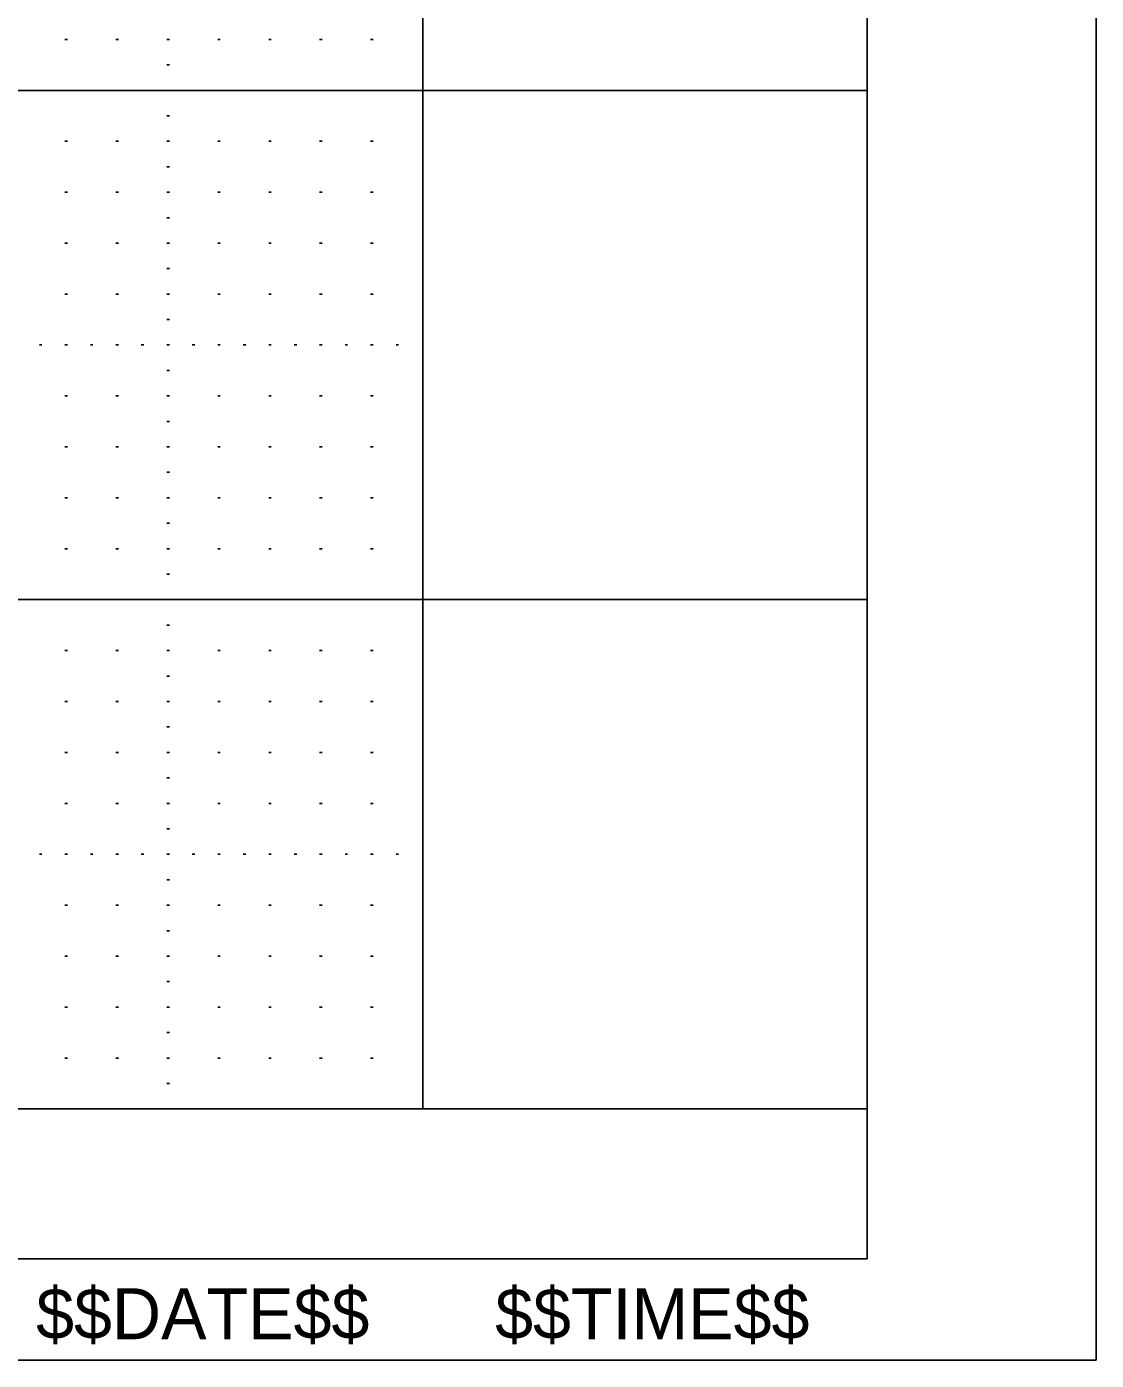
# Model space of a CAD drawing. Extents: x -1.3 to 32.1, y -0.2 to 20.7.
# Drawn here: x 29.967 to 32.067, y -0.2 to 2.418 of the extents above; entities that cross this region are included whole.
import ezdxf

# ---------------------------------------------------------------- set-up
doc = ezdxf.new("R2010")
doc.units = 0
for name, color, linetype in [('Level 1', 7, 'Continuous'), ('Level 4', 7, 'Continuous'), ('Level 48', 7, 'Continuous'), ('Level 5', 7, 'Continuous'), ('Level 63', 7, 'Continuous'), ('R_Border_Dark', 7, 'Continuous')]:
    doc.layers.add(name, color=color, linetype=linetype)

msp = doc.modelspace()

# ---------------------------------------------------------------- linework, layer by layer
at = {"layer": 'Level 1'}
for q in [(31.617, 20.545), (-0.001, -0.001)]:
    msp.add_line((31.617, -0.001), q, dxfattribs=at)
at = {"layer": 'Level 4'}
msp.add_line((31.617, 0.293), (-0.001, 0.293), dxfattribs=at)
at = {"layer": 'Level 5'}
for p, q in [((30.0425, 2.393), (30.0475, 2.393)), ((30.1425, 2.393), (30.1475, 2.393)), ((30.2425, 2.393), (30.2475, 2.393)), ((30.3425, 2.393), (30.3475, 2.393)), ((30.4425, 2.393), (30.4475, 2.393)), ((30.5425, 2.393), (30.5475, 2.393)), ((30.6425, 2.393), (30.6475, 2.393)), ((30.2425, 2.343), (30.2475, 2.343)), ((30.2425, 2.243), (30.2475, 2.243)), ((30.0425, 2.193), (30.0475, 2.193)), ((30.1425, 2.193), (30.1475, 2.193)), ((30.2425, 2.193), (30.2475, 2.193)), ((30.3425, 2.193), (30.3475, 2.193)), ((30.4425, 2.193), (30.4475, 2.193)), ((30.5425, 2.193), (30.5475, 2.193)), ((30.6425, 2.193), (30.6475, 2.193)), ((30.2425, 2.143), (30.2475, 2.143)), ((30.0425, 2.093), (30.0475, 2.093)), ((30.1425, 2.093), (30.1475, 2.093)), ((30.2425, 2.093), (30.2475, 2.093)), ((30.3425, 2.093), (30.3475, 2.093)), ((30.4425, 2.093), (30.4475, 2.093)), ((30.5425, 2.093), (30.5475, 2.093)), ((30.6425, 2.093), (30.6475, 2.093)), ((30.2425, 2.043), (30.2475, 2.043)), ((30.0425, 1.993), (30.0475, 1.993)), ((30.1425, 1.993), (30.1475, 1.993)), ((30.2425, 1.993), (30.2475, 1.993)), ((30.3425, 1.993), (30.3475, 1.993)), ((30.4425, 1.993), (30.4475, 1.993)), ((30.5425, 1.993), (30.5475, 1.993)), ((30.6425, 1.993), (30.6475, 1.993)), ((30.2425, 1.943), (30.2475, 1.943)), ((30.0425, 1.893), (30.0475, 1.893)), ((30.1425, 1.893), (30.1475, 1.893)), ((30.2425, 1.893), (30.2475, 1.893)), ((30.3425, 1.893), (30.3475, 1.893)), ((30.4425, 1.893), (30.4475, 1.893)), ((30.5425, 1.893), (30.5475, 1.893)), ((30.6425, 1.893), (30.6475, 1.893)), ((30.2425, 1.843), (30.2475, 1.843)), ((29.9925, 1.793), (29.9975, 1.793)), ((30.0425, 1.793), (30.0475, 1.793)), ((30.0925, 1.793), (30.0975, 1.793)), ((30.1425, 1.793), (30.1475, 1.793)), ((30.1925, 1.793), (30.1975, 1.793)), ((30.2425, 1.793), (30.2475, 1.793)), ((30.2925, 1.793), (30.2975, 1.793)), ((30.3425, 1.793), (30.3475, 1.793)), ((30.3925, 1.793), (30.3975, 1.793)), ((30.4425, 1.793), (30.4475, 1.793)), ((30.4925, 1.793), (30.4975, 1.793)), ((30.5425, 1.793), (30.5475, 1.793)), ((30.5925, 1.793), (30.5975, 1.793)), ((30.6425, 1.793), (30.6475, 1.793)), ((30.6925, 1.793), (30.6975, 1.793)), ((30.2425, 1.743), (30.2475, 1.743)), ((30.0425, 1.693), (30.0475, 1.693)), ((30.1425, 1.693), (30.1475, 1.693)), ((30.2425, 1.693), (30.2475, 1.693)), ((30.3425, 1.693), (30.3475, 1.693)), ((30.4425, 1.693), (30.4475, 1.693)), ((30.5425, 1.693), (30.5475, 1.693)), ((30.6425, 1.693), (30.6475, 1.693)), ((30.2425, 1.643), (30.2475, 1.643)), ((30.0425, 1.593), (30.0475, 1.593)), ((30.1425, 1.593), (30.1475, 1.593)), ((30.2425, 1.593), (30.2475, 1.593)), ((30.3425, 1.593), (30.3475, 1.593)), ((30.4425, 1.593), (30.4475, 1.593)), ((30.5425, 1.593), (30.5475, 1.593)), ((30.6425, 1.593), (30.6475, 1.593)), ((30.2425, 1.543), (30.2475, 1.543)), ((30.0425, 1.493), (30.0475, 1.493)), ((30.1425, 1.493), (30.1475, 1.493)), ((30.2425, 1.493), (30.2475, 1.493)), ((30.3425, 1.493), (30.3475, 1.493)), ((30.4425, 1.493), (30.4475, 1.493)), ((30.5425, 1.493), (30.5475, 1.493)), ((30.6425, 1.493), (30.6475, 1.493)), ((30.2425, 1.443), (30.2475, 1.443)), ((30.0425, 1.393), (30.0475, 1.393)), ((30.1425, 1.393), (30.1475, 1.393)), ((30.2425, 1.393), (30.2475, 1.393)), ((30.3425, 1.393), (30.3475, 1.393)), ((30.4425, 1.393), (30.4475, 1.393)), ((30.5425, 1.393), (30.5475, 1.393)), ((30.6425, 1.393), (30.6475, 1.393)), ((30.2425, 1.343), (30.2475, 1.343)), ((30.2425, 1.243), (30.2475, 1.243)), ((30.0425, 1.193), (30.0475, 1.193)), ((30.1425, 1.193), (30.1475, 1.193)), ((30.2425, 1.193), (30.2475, 1.193)), ((30.3425, 1.193), (30.3475, 1.193)), ((30.4425, 1.193), (30.4475, 1.193)), ((30.5425, 1.193), (30.5475, 1.193)), ((30.6425, 1.193), (30.6475, 1.193)), ((30.2425, 1.143), (30.2475, 1.143)), ((30.0425, 1.093), (30.0475, 1.093)), ((30.1425, 1.093), (30.1475, 1.093)), ((30.2425, 1.093), (30.2475, 1.093)), ((30.3425, 1.093), (30.3475, 1.093)), ((30.4425, 1.093), (30.4475, 1.093)), ((30.5425, 1.093), (30.5475, 1.093)), ((30.6425, 1.093), (30.6475, 1.093)), ((30.2425, 1.043), (30.2475, 1.043)), ((30.0425, 0.993), (30.0475, 0.993)), ((30.1425, 0.993), (30.1475, 0.993)), ((30.2425, 0.993), (30.2475, 0.993)), ((30.3425, 0.993), (30.3475, 0.993)), ((30.4425, 0.993), (30.4475, 0.993)), ((30.5425, 0.993), (30.5475, 0.993)), ((30.6425, 0.993), (30.6475, 0.993)), ((30.2425, 0.943), (30.2475, 0.943)), ((30.0425, 0.893), (30.0475, 0.893)), ((30.1425, 0.893), (30.1475, 0.893)), ((30.2425, 0.893), (30.2475, 0.893)), ((30.3425, 0.893), (30.3475, 0.893)), ((30.4425, 0.893), (30.4475, 0.893)), ((30.5425, 0.893), (30.5475, 0.893)), ((30.6425, 0.893), (30.6475, 0.893)), ((30.2425, 0.843), (30.2475, 0.843)), ((29.9925, 0.793), (29.9975, 0.793)), ((30.0425, 0.793), (30.0475, 0.793)), ((30.0925, 0.793), (30.0975, 0.793)), ((30.1425, 0.793), (30.1475, 0.793)), ((30.1925, 0.793), (30.1975, 0.793)), ((30.2425, 0.793), (30.2475, 0.793)), ((30.2925, 0.793), (30.2975, 0.793)), ((30.3425, 0.793), (30.3475, 0.793)), ((30.3925, 0.793), (30.3975, 0.793)), ((30.4425, 0.793), (30.4475, 0.793)), ((30.4925, 0.793), (30.4975, 0.793)), ((30.5425, 0.793), (30.5475, 0.793)), ((30.5925, 0.793), (30.5975, 0.793)), ((30.6425, 0.793), (30.6475, 0.793)), ((30.6925, 0.793), (30.6975, 0.793)), ((30.2425, 0.743), (30.2475, 0.743)), ((30.0425, 0.693), (30.0475, 0.693)), ((30.1425, 0.693), (30.1475, 0.693)), ((30.2425, 0.693), (30.2475, 0.693)), ((30.3425, 0.693), (30.3475, 0.693)), ((30.4425, 0.693), (30.4475, 0.693)), ((30.5425, 0.693), (30.5475, 0.693)), ((30.6425, 0.693), (30.6475, 0.693)), ((30.2425, 0.643), (30.2475, 0.643)), ((30.0425, 0.593), (30.0475, 0.593)), ((30.1425, 0.593), (30.1475, 0.593)), ((30.2425, 0.593), (30.2475, 0.593)), ((30.3425, 0.593), (30.3475, 0.593)), ((30.4425, 0.593), (30.4475, 0.593)), ((30.5425, 0.593), (30.5475, 0.593)), ((30.6425, 0.593), (30.6475, 0.593)), ((30.2425, 0.543), (30.2475, 0.543)), ((30.0425, 0.493), (30.0475, 0.493)), ((30.1425, 0.493), (30.1475, 0.493)), ((30.2425, 0.493), (30.2475, 0.493)), ((30.3425, 0.493), (30.3475, 0.493)), ((30.4425, 0.493), (30.4475, 0.493)), ((30.5425, 0.493), (30.5475, 0.493)), ((30.6425, 0.493), (30.6475, 0.493)), ((30.2425, 0.443), (30.2475, 0.443)), ((30.0425, 0.393), (30.0475, 0.393)), ((30.1425, 0.393), (30.1475, 0.393)), ((30.2425, 0.393), (30.2475, 0.393)), ((30.3425, 0.393), (30.3475, 0.393)), ((30.4425, 0.393), (30.4475, 0.393)), ((30.5425, 0.393), (30.5475, 0.393)), ((30.6425, 0.393), (30.6475, 0.393)), ((30.2425, 0.343), (30.2475, 0.343))]:
    msp.add_line(p, q, dxfattribs=at)
at = {"layer": 'Level 63'}
msp.add_lwpolyline([(-1.263, -0.2005), (32.067, -0.2005), (32.067, 20.7465), (-1.263, 20.7465)], close=True, dxfattribs=at)
msp.add_lwpolyline([(30.745, 8.293), (30.745, 0.293), (0.745, 0.293), (0.745, 8.293)], dxfattribs=at)
at = {"layer": 'R_Border_Dark'}
for p, q in [((30.745, 0.293), (30.745, 8.293)), ((31.617, 2.293), (-0.001, 2.293)), ((31.617, 1.293), (-0.001, 1.293))]:
    msp.add_line(p, q, dxfattribs=at)
msp.add_lwpolyline([(30.745, 8.293), (30.745, 0.293), (0.745, 0.293), (0.745, 8.293)], dxfattribs=at)

# ---------------------------------------------------------------- texts
at = {"layer": 'Level 48'}
for s, p in [('$$DATE$$', (29.986, -0.159)), ('$$TIME$$', (30.887, -0.159))]:
    msp.add_text(s, height=0.1, dxfattribs=at).set_placement(p)

doc.saveas('drawing.dxf')
